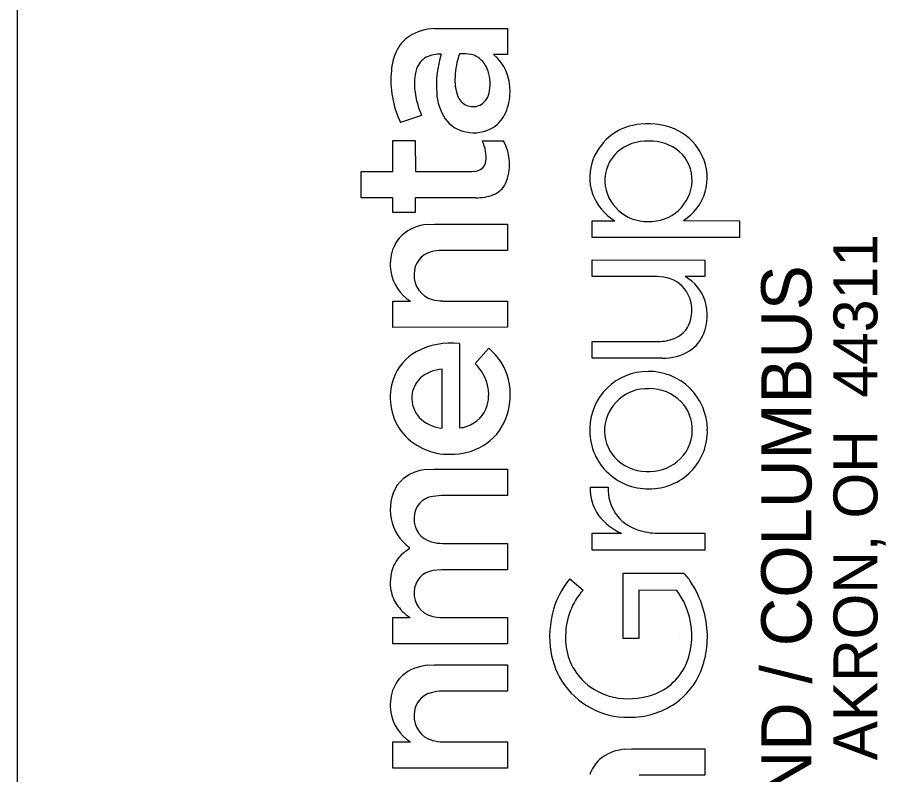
# Model space of a CAD drawing. Extents: x 0 to 1700, y 0 to 1100.
# Drawn here: x 1600 to 1649.21, y 167.17 to 210.08 of the extents above; entities that cross this region are included whole.
import ezdxf

# ---------------------------------------------------------------- set-up
doc = ezdxf.new("R2010")
doc.units = 0
doc.layers.add('SH_Border', color=7, linetype='Continuous')
doc.layers.add('SH_Data', color=7, linetype='Continuous')

msp = doc.modelspace()

# ---------------------------------------------------------------- linework, layer by layer
at = {"layer": 'SH_Border'}
msp.add_line((1600, 25), (1600, 1075), dxfattribs=at)
at = {"layer": 'SH_Data'}
for p, q in [((1623.633, 209.45), (1627.776, 209.459)), ((1627.776, 209.459), (1627.786, 207.978)), ((1627.786, 207.978), (1626.986, 207.978)), ((1622.909, 204.522), (1621.715, 204.116)), ((1621.271, 201.352), (1621.274, 203.104)), ((1621.274, 203.104), (1622.554, 203.104)), ((1622.554, 203.104), (1622.559, 201.352)), ((1626.348, 203.08), (1627.555, 203.08)), ((1619.482, 201.35), (1621.271, 201.352)), ((1619.482, 199.86), (1619.482, 201.35)), ((1622.559, 201.352), (1625.749, 201.352)), ((1625.749, 201.352), (1626.002, 201.375)), ((1621.271, 199.859), (1619.482, 199.86)), ((1621.271, 199.033), (1621.271, 199.859)), ((1625.984, 199.859), (1622.554, 199.858)), ((1622.554, 199.858), (1622.554, 199.033)), ((1622.554, 199.033), (1621.271, 199.033)), ((1623.219, 198.343), (1623.645, 198.366)), ((1623.645, 198.366), (1627.785, 198.366)), ((1627.785, 198.366), (1627.786, 196.877)), ((1632.576, 197.607), (1632.576, 198.557)), ((1632.576, 198.557), (1633.855, 198.557)), ((1637.746, 198.566), (1640.929, 198.554)), ((1640.929, 198.554), (1640.921, 197.607)), ((1640.921, 197.607), (1632.576, 197.607)), ((1627.786, 196.877), (1624.07, 196.873)), ((1632.576, 195.4), (1632.576, 196.336)), ((1632.576, 196.336), (1638.955, 196.332)), ((1638.955, 196.332), (1638.954, 195.398)), ((1636.245, 195.398), (1632.576, 195.4)), ((1636.64, 195.364), (1636.245, 195.398)), ((1638.954, 195.398), (1637.845, 195.398)), ((1621.271, 194.008), (1622.276, 194.01)), ((1621.271, 192.517), (1621.271, 194.008)), ((1624.111, 194.01), (1627.785, 194.01)), ((1627.785, 194.01), (1627.786, 192.522)), ((1627.786, 192.522), (1621.271, 192.517)), ((1625.054, 191.604), (1625.059, 186.829)), ((1632.577, 191.722), (1636.453, 191.725)), ((1632.583, 190.771), (1632.577, 191.722)), ((1625.941, 190.463), (1626.711, 191.331)), ((1636.537, 190.771), (1632.583, 190.771)), ((1624.072, 186.822), (1624.072, 190.148)), ((1624.008, 186.814), (1624.072, 186.822)), ((1623.165, 184.457), (1623.629, 184.484)), ((1623.629, 184.484), (1627.779, 184.484)), ((1627.779, 184.484), (1627.786, 182.991)), ((1632.466, 183.453), (1633.489, 183.453)), ((1624.029, 182.99), (1623.551, 182.941)), ((1627.786, 182.991), (1624.029, 182.99)), ((1632.576, 179.9), (1632.576, 180.85)), ((1632.576, 180.85), (1634.238, 180.85)), ((1636.302, 180.851), (1638.955, 180.848)), ((1638.955, 180.848), (1638.952, 179.9)), ((1624.109, 180.276), (1627.786, 180.274)), ((1627.786, 180.274), (1627.786, 178.784)), ((1622.222, 179.961), (1622.228, 180.036)), ((1638.952, 179.9), (1632.576, 179.9)), ((1624.045, 178.783), (1623.572, 178.737)), ((1627.786, 178.784), (1624.045, 178.783)), ((1631.318, 178.274), (1632.057, 177.621)), ((1634.34, 178.592), (1637.758, 178.596)), ((1634.34, 174.889), (1634.34, 178.592)), ((1635.224, 177.62), (1635.216, 174.888)), ((1637.368, 177.614), (1635.224, 177.62)), ((1621.271, 174.576), (1621.272, 176.069)), ((1621.272, 176.069), (1622.257, 176.069)), ((1624.103, 176.069), (1627.786, 176.068)), ((1627.786, 176.068), (1627.786, 174.578)), ((1635.216, 174.888), (1634.34, 174.889)), ((1637.5, 175), (1637.5, 175)), ((1627.786, 174.578), (1621.271, 174.576)), ((1623.219, 173.368), (1623.645, 173.391)), ((1623.645, 173.391), (1627.785, 173.391)), ((1627.785, 173.391), (1627.786, 171.902)), ((1627.786, 171.902), (1624.07, 171.898)), ((1621.271, 169.033), (1622.276, 169.036)), ((1621.271, 167.543), (1621.271, 169.033)), ((1624.111, 169.036), (1627.785, 169.036)), ((1627.785, 169.036), (1627.786, 167.548)), ((1634.392, 168.61), (1634.817, 168.633)), ((1634.817, 168.633), (1638.958, 168.633)), ((1638.958, 168.633), (1638.958, 167.144)), ((1627.786, 167.548), (1621.271, 167.543))]:
    msp.add_line(p, q, dxfattribs=at)
for points in [[(1623.633, 209.45), (1627.776, 209.459), (1627.786, 207.978)], [(1627.786, 207.978), (1626.986, 207.978)], [(1622.909, 204.522), (1621.715, 204.116)], [(1625.984, 199.859), (1622.554, 199.858), (1622.554, 199.033), (1621.271, 199.033), (1621.271, 199.859), (1619.482, 199.86), (1619.482, 201.35), (1621.271, 201.352), (1621.274, 203.104), (1622.554, 203.104), (1622.559, 201.352), (1625.749, 201.352), (1626.002, 201.375)], [(1626.348, 203.08), (1627.555, 203.08)], [(1623.219, 198.343), (1623.645, 198.366), (1627.785, 198.366), (1627.786, 196.877), (1624.07, 196.873)], [(1637.746, 198.566), (1640.929, 198.554), (1640.921, 197.607), (1632.576, 197.607)], [(1632.576, 197.607), (1632.576, 198.557), (1633.855, 198.557)], [(1636.64, 195.364), (1636.245, 195.398), (1632.576, 195.4), (1632.576, 196.336), (1638.955, 196.332), (1638.954, 195.398), (1637.845, 195.398)], [(1621.271, 192.517), (1621.271, 194.008), (1622.276, 194.01)], [(1624.111, 194.01), (1627.785, 194.01), (1627.786, 192.522), (1621.271, 192.517)], [(1625.054, 191.604), (1625.059, 186.829)], [(1636.537, 190.771), (1632.583, 190.771), (1632.577, 191.722), (1636.453, 191.725)], [(1625.941, 190.463), (1626.711, 191.331)], [(1624.008, 186.814), (1624.072, 186.822), (1624.072, 190.148)], [(1623.165, 184.457), (1623.629, 184.484), (1627.779, 184.484), (1627.786, 182.991), (1624.029, 182.99), (1623.551, 182.941)], [(1632.466, 183.453), (1633.489, 183.453)], [(1636.302, 180.851), (1638.955, 180.848), (1638.952, 179.9), (1632.576, 179.9)], [(1632.576, 179.9), (1632.576, 180.85), (1634.238, 180.85)], [(1624.109, 180.276), (1627.786, 180.274), (1627.786, 178.784), (1624.045, 178.783), (1623.572, 178.737)], [(1622.222, 179.961), (1622.228, 180.036)], [(1631.318, 178.274), (1632.057, 177.621)], [(1637.368, 177.614), (1635.224, 177.62), (1635.216, 174.888), (1634.34, 174.889), (1634.34, 178.592), (1637.758, 178.596)], [(1621.271, 174.576), (1621.272, 176.069), (1622.257, 176.069)], [(1624.103, 176.069), (1627.786, 176.068), (1627.786, 174.578), (1621.271, 174.576)], [(1623.219, 173.368), (1623.645, 173.391), (1627.785, 173.391), (1627.786, 171.902), (1624.07, 171.898)], [(1621.271, 167.543), (1621.271, 169.033), (1622.276, 169.036)], [(1624.111, 169.036), (1627.785, 169.036), (1627.786, 167.548), (1621.271, 167.543)], [(1634.392, 168.61), (1634.817, 168.633), (1638.958, 168.633), (1638.958, 167.144), (1635.242, 167.14)]]:
    msp.add_lwpolyline(points, dxfattribs=at)
for centre, radius, start, end in [((1623.726, 206.628), 2.823, 91.8942, 122.6317), ((1623.726, 206.628), 2.823, 91.8942, 122.6317), ((1623.423, 207.234), 2.151, 124.537, 155.6594), ((1623.423, 207.234), 2.151, 124.537, 155.6594), ((1624.412, 206.806), 3.228, 155.9764, 175.3149), ((1624.412, 206.806), 3.228, 155.9764, 175.3149), ((1623.763, 206.78), 1.2, 119.4252, 161.6629), ((1623.763, 206.78), 1.2, 119.4252, 161.6629), ((1623.893, 206.389), 1.607, 85.3802, 116.6222), ((1623.893, 206.389), 1.607, 85.3802, 116.6222), ((1629.394, 206.254), 5.645, 162.0821, 184.5285), ((1629.394, 206.254), 5.645, 162.0821, 184.5285), ((1629.007, 206.566), 4.205, 159.8366, 178.0362), ((1629.007, 206.566), 4.205, 159.8366, 178.0362), ((1625.255, 205.371), 2.651, 79.6696, 94.2322), ((1625.255, 205.371), 2.651, 79.6696, 94.2322), ((1625.446, 206.822), 1.192, 56.8913, 76.2149), ((1625.446, 206.822), 1.192, 56.8913, 76.2149), ((1625.26, 206.592), 1.486, 17.5984, 55.7282), ((1625.26, 206.592), 1.486, 17.5984, 55.7282), ((1625.276, 205.957), 2.647, 358.0746, 49.762), ((1625.276, 205.957), 2.647, 358.0746, 49.762), ((1626.82, 206.539), 5.65, 174.6101, 205.3899), ((1626.82, 206.539), 5.65, 174.6101, 205.3899), ((1625.379, 206.323), 2.879, 163.1369, 188.1675), ((1625.379, 206.323), 2.879, 163.1369, 188.1675), ((1627.328, 206.515), 2.531, 175.5903, 199.8857), ((1627.328, 206.515), 2.531, 175.5903, 199.8857), ((1624.58, 206.32), 2.217, 345.9408, 18.9919), ((1624.58, 206.32), 2.217, 345.9408, 18.9919), ((1627.363, 206.487), 4.867, 186.7598, 203.7981), ((1627.363, 206.487), 4.867, 186.7598, 203.7981), ((1626.639, 205.937), 2.876, 182.5676, 213.7144), ((1626.639, 205.937), 2.876, 182.5676, 213.7144), ((1625.76, 205.997), 0.995, 295.2883, 347.4639), ((1625.76, 205.997), 0.995, 295.2883, 347.4639), ((1625.093, 205.839), 2.828, 336.016, 0.5951), ((1625.093, 205.839), 2.828, 336.016, 0.5951), ((1625.821, 205.943), 0.92, 198.2844, 293.3081), ((1625.821, 205.943), 0.92, 198.2844, 293.3081), ((1625.743, 205.391), 1.828, 215.0668, 259.8133), ((1625.743, 205.391), 1.828, 215.0668, 259.8133), ((1625.876, 205.485), 1.969, 303.4436, 336.18), ((1625.876, 205.485), 1.969, 303.4436, 336.18), ((1625.877, 205.655), 2.113, 257.5256, 300.882), ((1625.877, 205.655), 2.113, 257.5256, 300.882), ((1635.54, 200.912), 3.122, 93.9866, 158.3119), ((1635.54, 200.912), 3.122, 93.9866, 158.3119), ((1635.779, 200.325), 3.729, 62.6889, 97.0135), ((1635.779, 200.325), 3.729, 62.6889, 97.0135), ((1636.062, 200.957), 3.038, 25.0657, 61.9602), ((1636.062, 200.957), 3.038, 25.0657, 61.9602), ((1624.313, 202.099), 2.259, 10.1545, 25.723), ((1624.313, 202.099), 2.259, 10.1545, 25.723), ((1625.151, 201.753), 2.746, 336.589, 28.8991), ((1625.151, 201.753), 2.746, 336.589, 28.8991), ((1635.69, 200.508), 2.567, 87.8965, 131.1812), ((1635.69, 200.508), 2.567, 87.8965, 131.1812), ((1635.875, 200.511), 2.564, 49.9089, 92.0363), ((1635.875, 200.511), 2.564, 49.9089, 92.0363), ((1624.786, 202.182), 1.778, 351.914, 10.2059), ((1624.786, 202.182), 1.778, 351.914, 10.2059), ((1635.46, 200.837), 2.169, 132.3289, 182.0949), ((1635.46, 200.837), 2.169, 132.3289, 182.0949), ((1636.077, 200.866), 2.163, 358.0487, 47.9447), ((1636.077, 200.866), 2.163, 358.0487, 47.9447), ((1636.225, 201.002), 2.871, 301.9776, 25.6418), ((1636.225, 201.002), 2.871, 301.9776, 25.6418), ((1625.919, 202.001), 0.632, 277.6142, 353.7918), ((1625.919, 202.001), 0.632, 277.6142, 353.7918), ((1635.348, 201.008), 2.907, 158.656, 198.171), ((1635.348, 201.008), 2.907, 158.656, 198.171), ((1635.859, 200.901), 2.383, 267.3149, 357.4019), ((1635.859, 200.901), 2.383, 267.3149, 357.4019), ((1626.456, 201.306), 1.375, 292.6889, 332.0598), ((1626.456, 201.306), 1.375, 292.6889, 332.0598), ((1635.676, 200.907), 2.388, 183.5974, 271.7045), ((1635.676, 200.907), 2.388, 183.5974, 271.7045), ((1626.044, 202.428), 2.569, 268.6727, 291.5235), ((1626.044, 202.428), 2.569, 268.6727, 291.5235), ((1635.515, 201.217), 3.135, 200.8399, 238.0162), ((1635.515, 201.217), 3.135, 200.8399, 238.0162), ((1623.435, 195.858), 2.494, 94.9706, 130.2248), ((1623.435, 195.858), 2.494, 94.9706, 130.2248), ((1623.174, 196.275), 2.008, 132.2238, 161.6823), ((1623.174, 196.275), 2.008, 132.2238, 161.6823), ((1623.936, 196.054), 2.801, 162.274, 187.7917), ((1623.936, 196.054), 2.801, 162.274, 187.7917), ((1624.054, 194.573), 2.3, 89.6051, 105.3303), ((1624.054, 194.573), 2.3, 89.6051, 105.3303), ((1623.741, 195.578), 1.249, 103.6868, 182.214), ((1623.741, 195.578), 1.249, 103.6868, 182.214), ((1623.513, 196.045), 2.381, 188.9646, 238.6987), ((1623.513, 196.045), 2.381, 188.9646, 238.6987), ((1623.868, 195.423), 1.378, 175.5844, 255.1382), ((1623.868, 195.423), 1.378, 175.5844, 255.1382), ((1636.355, 193.499), 1.886, 33.5008, 81.3295), ((1636.355, 193.499), 1.886, 33.5008, 81.3295), ((1636.62, 193.242), 2.48, 17.6221, 60.3897), ((1636.62, 193.242), 2.48, 17.6221, 60.3897), ((1636.207, 193.475), 2.024, 346.5618, 31.7539), ((1636.207, 193.475), 2.024, 346.5618, 31.7539), ((1624.092, 196.118), 2.107, 254.0891, 270.5284), ((1624.092, 196.118), 2.107, 254.0891, 270.5284), ((1636.172, 193.207), 2.919, 339.162, 15.6148), ((1636.172, 193.207), 2.919, 339.162, 15.6148), ((1636.685, 193.308), 1.521, 294.6321, 348.4863), ((1636.685, 193.308), 1.521, 294.6321, 348.4863), ((1636.374, 194.041), 2.317, 271.952, 294.0894), ((1636.374, 194.041), 2.317, 271.952, 294.0894), ((1636.95, 192.951), 2.101, 303.1039, 338.1561), ((1636.95, 192.951), 2.101, 303.1039, 338.1561), ((1624.588, 187.437), 4.193, 83.6212, 118.2845), ((1624.588, 187.437), 4.193, 83.6212, 118.2845), ((1623.947, 188.684), 2.791, 118.8294, 160.6224), ((1623.947, 188.684), 2.791, 118.8294, 160.6224), ((1624.7, 188.815), 3.221, 13.5328, 51.3627), ((1624.7, 188.815), 3.221, 13.5328, 51.3627), ((1636.605, 193.628), 2.857, 268.627, 301.4778), ((1636.605, 193.628), 2.857, 268.627, 301.4778), ((1624.017, 188.509), 2.743, 19.0387, 45.4432), ((1624.017, 188.509), 2.743, 19.0387, 45.4432), ((1624.22, 188.035), 2.118, 94.0131, 130.8806), ((1624.22, 188.035), 2.118, 94.0131, 130.8806), ((1635.717, 186.742), 3.276, 89.4821, 178.7775), ((1635.717, 186.742), 3.276, 89.4821, 178.7775), ((1635.791, 186.707), 3.312, 0.4227, 90.7613), ((1635.791, 186.707), 3.312, 0.4227, 90.7613), ((1624.348, 188.537), 3.219, 160.5214, 215.7815), ((1624.348, 188.537), 3.219, 160.5214, 215.7815), ((1623.851, 188.545), 1.492, 132.9855, 177.1802), ((1623.851, 188.545), 1.492, 132.9855, 177.1802), ((1624.145, 188.692), 3.79, 339.3543, 13.3771), ((1624.145, 188.692), 3.79, 339.3543, 13.3771), ((1624.362, 188.716), 2.35, 344.6072, 17.0067), ((1624.362, 188.716), 2.35, 344.6072, 17.0067), ((1635.698, 186.622), 2.423, 87.6883, 175.017), ((1635.698, 186.622), 2.423, 87.6883, 175.017), ((1635.83, 186.518), 2.526, 44.912, 90.7591), ((1635.83, 186.518), 2.526, 44.912, 90.7591), ((1623.912, 188.483), 1.557, 175.0014, 223.2876), ((1623.912, 188.483), 1.557, 175.0014, 223.2876), ((1624.948, 188.589), 1.752, 288.0108, 343.5536), ((1624.948, 188.589), 1.752, 288.0108, 343.5536), ((1635.978, 186.726), 2.274, 358.3228, 43.8349), ((1635.978, 186.726), 2.274, 358.3228, 43.8349), ((1624.273, 188.913), 2.116, 225.0645, 262.797), ((1624.273, 188.913), 2.116, 225.0645, 262.797), ((1624.774, 188.491), 3.13, 300.9439, 338.7322), ((1624.774, 188.491), 3.13, 300.9439, 338.7322), ((1624.454, 188.758), 3.436, 217.7434, 271.6561), ((1624.454, 188.758), 3.436, 217.7434, 271.6561), ((1625.064, 187.839), 1.01, 269.7004, 294.8729), ((1625.064, 187.839), 1.01, 269.7004, 294.8729), ((1635.742, 186.67), 3.303, 177.5373, 270.9452), ((1635.742, 186.67), 3.303, 177.5373, 270.9452), ((1635.542, 186.656), 2.265, 175.5147, 221.4205), ((1635.542, 186.656), 2.265, 175.5147, 221.4205), ((1635.836, 186.636), 3.268, 269.3083, 1.6791), ((1635.836, 186.636), 3.268, 269.3083, 1.6791), ((1635.966, 186.687), 2.286, 308.9038, 359.3095), ((1635.966, 186.687), 2.286, 308.9038, 359.3095), ((1624.602, 188.851), 3.528, 269.2053, 300.3357), ((1624.602, 188.851), 3.528, 269.2053, 300.3357), ((1635.699, 186.867), 2.523, 222.6626, 268.3733), ((1635.699, 186.867), 2.523, 222.6626, 268.3733), ((1635.783, 186.929), 2.589, 266.5531, 308.6725), ((1635.783, 186.929), 2.589, 266.5531, 308.6725), ((1623.319, 182.202), 2.261, 93.9112, 142.3072), ((1623.319, 182.202), 2.261, 93.9112, 142.3072), ((1623.793, 182.186), 2.66, 148.2879, 233.9556), ((1623.793, 182.186), 2.66, 148.2879, 233.9556), ((1634.939, 183.331), 2.476, 177.1621, 216.2802), ((1634.939, 183.331), 2.476, 177.1621, 216.2802), ((1635.867, 183.319), 2.382, 176.7699, 252.1504), ((1635.867, 183.319), 2.382, 176.7699, 252.1504), ((1623.692, 181.75), 1.2, 96.7576, 181.6251), ((1623.692, 181.75), 1.2, 96.7576, 181.6251), ((1623.788, 181.621), 1.299, 175.8157, 256.1672), ((1623.788, 181.621), 1.299, 175.8157, 256.1672), ((1635.488, 183.777), 3.183, 216.9153, 246.8862), ((1635.488, 183.777), 3.183, 216.9153, 246.8862), ((1636.345, 184.587), 3.736, 251.1388, 269.3469), ((1636.345, 184.587), 3.736, 251.1388, 269.3469), ((1624.085, 182.527), 2.25, 254.3463, 270.6103), ((1624.085, 182.527), 2.25, 254.3463, 270.6103), ((1623.19, 178.133), 2.068, 117.9163, 139.243), ((1623.19, 178.133), 2.068, 117.9163, 139.243), ((1623.097, 178.226), 1.937, 139.5245, 154.847), ((1623.097, 178.226), 1.937, 139.5245, 154.847), ((1623.572, 178.06), 2.439, 156.0638, 187.3493), ((1623.572, 178.06), 2.439, 156.0638, 187.3493), ((1623.711, 177.528), 1.217, 96.5532, 179.949), ((1623.711, 177.528), 1.217, 96.5532, 179.949), ((1635.081, 175.093), 4.928, 139.7948, 159.137), ((1635.081, 175.093), 4.928, 139.7948, 159.137), ((1636.249, 176.969), 2.219, 30.9891, 47.161), ((1636.249, 176.969), 2.219, 30.9891, 47.161), ((1623.23, 177.987), 2.091, 186.5579, 213.3885), ((1623.23, 177.987), 2.091, 186.5579, 213.3885), ((1633.546, 175.009), 5.553, 25.3031, 33.9618), ((1633.546, 175.009), 5.553, 25.3031, 33.9618), ((1623.804, 177.431), 1.314, 175.722, 255.7863), ((1623.804, 177.431), 1.314, 175.722, 255.7863), ((1634.95, 175.04), 3.877, 138.258, 179.7006), ((1634.95, 175.04), 3.877, 138.258, 179.7006), ((1633.944, 175.049), 4.278, 10.0751, 36.8319), ((1633.944, 175.049), 4.278, 10.0751, 36.8319), ((1633.52, 174.993), 5.583, 8.8034, 25.3348), ((1633.52, 174.993), 5.583, 8.8034, 25.3348), ((1623.943, 178.539), 2.99, 214.7043, 235.6872), ((1623.943, 178.539), 2.99, 214.7043, 235.6872), ((1635.935, 174.984), 5.768, 161.1438, 185.6281), ((1635.935, 174.984), 5.768, 161.1438, 185.6281), ((1624.097, 178.259), 2.19, 253.6672, 270.1498), ((1624.097, 178.259), 2.19, 253.6672, 270.1498), ((1634.212, 175.028), 4.018, 333.4669, 11.0367), ((1634.212, 175.028), 4.018, 333.4669, 11.0367), ((1633.782, 174.989), 5.325, 338.2887, 9.2855), ((1633.782, 174.989), 5.325, 338.2887, 9.2855), ((1634.406, 174.866), 3.338, 176.6658, 223.6912), ((1634.406, 174.866), 3.338, 176.6658, 223.6912), ((1634.668, 174.85), 4.493, 185.5077, 212.0129), ((1634.668, 174.85), 4.493, 185.5077, 212.0129), ((1623.435, 170.884), 2.494, 94.9706, 130.2248), ((1623.435, 170.884), 2.494, 94.9706, 130.2248), ((1634.934, 174.773), 3.26, 282.8815, 331.8147), ((1634.934, 174.773), 3.26, 282.8815, 331.8147), ((1623.174, 171.301), 2.008, 132.2238, 161.6823), ((1623.174, 171.301), 2.008, 132.2238, 161.6823), ((1634.918, 174.584), 4.12, 305.0306, 337.6757), ((1634.918, 174.584), 4.12, 305.0306, 337.6757), ((1634.606, 174.874), 4.454, 212.7022, 270.714), ((1634.606, 174.874), 4.454, 212.7022, 270.714), ((1634.523, 175.006), 3.519, 224.0215, 253.88), ((1634.523, 175.006), 3.519, 224.0215, 253.88), ((1623.936, 171.079), 2.801, 162.274, 187.7917), ((1623.936, 171.079), 2.801, 162.274, 187.7917), ((1623.741, 170.603), 1.249, 103.6868, 182.214), ((1623.741, 170.603), 1.249, 103.6868, 182.214), ((1624.054, 169.598), 2.3, 89.6051, 105.3303), ((1624.054, 169.598), 2.3, 89.6051, 105.3303), ((1634.659, 175.627), 4.154, 254.4535, 283.9512), ((1634.659, 175.627), 4.154, 254.4535, 283.9512), ((1634.715, 174.989), 4.569, 269.3273, 304.1963), ((1634.715, 174.989), 4.569, 269.3273, 304.1963), ((1623.513, 171.071), 2.381, 188.9646, 238.6987), ((1623.513, 171.071), 2.381, 188.9646, 238.6987), ((1623.868, 170.449), 1.378, 175.5844, 255.1382), ((1623.868, 170.449), 1.378, 175.5844, 255.1382), ((1624.092, 171.143), 2.107, 254.0891, 270.5284), ((1624.092, 171.143), 2.107, 254.0891, 270.5284), ((1634.608, 166.125), 2.494, 94.9706, 130.2248), ((1634.608, 166.125), 2.494, 94.9706, 130.2248), ((1634.347, 166.543), 2.008, 132.2238, 161.6823), ((1634.347, 166.543), 2.008, 132.2238, 161.6823)]:
    msp.add_arc(centre, radius, start, end, dxfattribs=at)

# ---------------------------------------------------------------- texts
for s, height, p in [('450 GRANT ST., AKRON, OH  44311', 2.49231, (1648.744, 141.869)), ('AKRON / CLEVELAND / COLUMBUS', 2.84845, (1645.006, 131.9))]:
    msp.add_text(s, height=height, rotation=90, dxfattribs=at).set_placement(p)

doc.saveas('drawing.dxf')
